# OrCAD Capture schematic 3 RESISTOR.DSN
size A
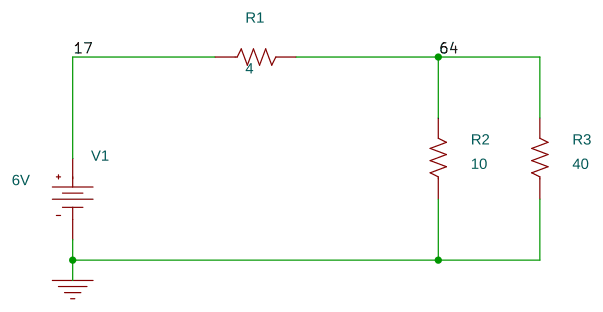
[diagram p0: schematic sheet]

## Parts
R1  4  [AX/RC05]
R2  10  [AX/RC05]
R3  40  [AX/RC05]
V1  VDC

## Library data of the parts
R1-R3 = R
V1 = VDC: DC: 6V

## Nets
0: R2.1 R3.1 V1.1(-)
17: R1.1 V1.0(+)
64: R1.2 R2.2 R3.2
